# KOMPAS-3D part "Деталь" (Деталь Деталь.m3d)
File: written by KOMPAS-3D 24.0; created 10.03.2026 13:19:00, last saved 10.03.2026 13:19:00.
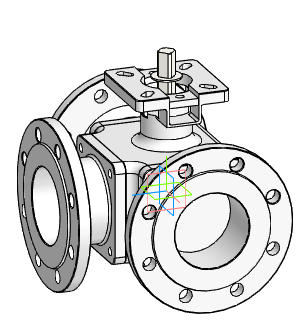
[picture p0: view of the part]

Document properties: Автор: R2D2; Полное имя файла: E:\Работа\Зайцев\BV3232P(4pc)-FP-3WL-F-ISO-H Кран шаровой DN.ru Ду15-100 Ру16\DN100\исходные материалы\Деталь Деталь.m3d

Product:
- Body: Твердое тело1  | qty 1
- Part/product: Деталь
    additional columns: Типовые

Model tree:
1. Твердое тело1  (labels: Твердое тело1)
